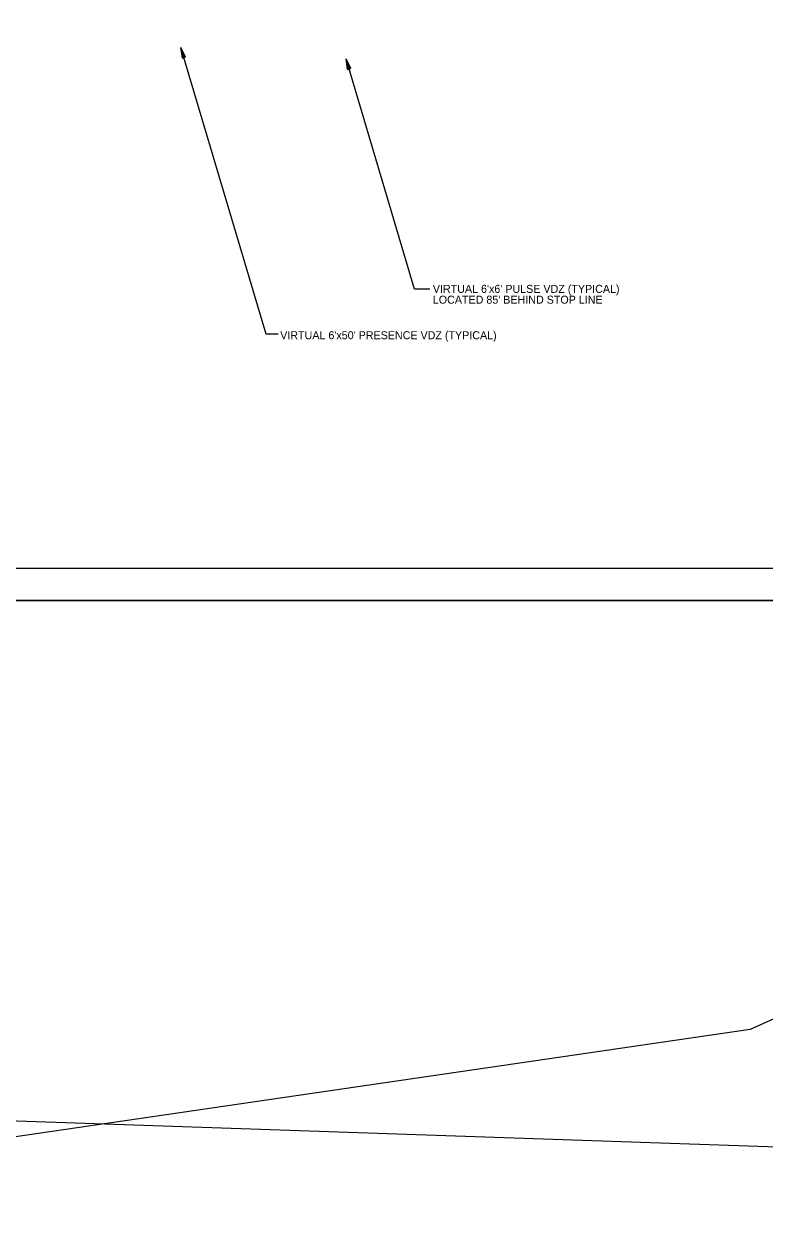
# Model space of a CAD drawing. Extents: x 660063 to 664816, y 641756 to 643817.
# Drawn here: x 661905.5 to 662183.1, y 642013.5 to 642464.6 of the extents above; entities that cross this region are included whole.
import ezdxf

# ---------------------------------------------------------------- set-up
doc = ezdxf.new("R2010")
doc.units = 0
for name, color, linetype in [('Default', 7, 'Continuous'), ('R_Border', 7, 'Continuous'), ('R_No Plot', 7, 'Continuous'), ('T_Drafting', 7, 'Continuous')]:
    doc.layers.add(name, color=color, linetype=linetype)

msp = doc.modelspace()

# ---------------------------------------------------------------- linework, layer by layer
at = {"layer": 'Default'}
for points in [[(662978.12, 642248.52), (662628.42, 642290.7), (662177.59, 642087.82)], [(662177.59, 642087.82), (661668.75, 642013.51), (660133.51, 642066.06)], [(663581.19, 642087.82), (663072.35, 642013.51), (661537.11, 642066.06)]]:
    msp.add_lwpolyline(points, dxfattribs=at)
at = {"layer": 'R_Border'}
msp.add_line((662396.53, 642260.59), (661447.99, 642260.59), dxfattribs=at)
at = {"layer": 'R_No Plot'}
msp.add_line((661410.79, 642248.66), (662410.79, 642248.66), dxfattribs=at)
msp.add_lwpolyline([(661410.77, 642888.66), (662410.79, 642888.66), (662410.79, 642248.64), (661410.77, 642248.64)], close=True, dxfattribs=at)
at = {"layer": 'T_Drafting'}
for p, q in [((661996.13, 642348.46), (661964.24, 642455.87)), ((661964.8, 642451.87), (661964.24, 642455.87)), ((661965.95, 642452.21), (661964.24, 642455.87)), ((661964.9, 642451.89), (661964.43, 642455.23)), ((661965.86, 642452.18), (661964.43, 642455.23)), ((661965.76, 642452.15), (661964.63, 642454.57)), ((661965, 642451.92), (661964.63, 642454.57)), ((661965.09, 642451.95), (661964.82, 642453.93)), ((661965.66, 642452.12), (661964.82, 642453.93)), ((661965.57, 642452.09), (661965.01, 642453.28)), ((661965.19, 642451.98), (661965.01, 642453.28)), ((661964.8, 642451.87), (661965.95, 642452.21)), ((661965.47, 642452.06), (661965.2, 642452.64)), ((661965.29, 642452.01), (661965.2, 642452.64)), ((662026.71, 642447.63), (662026.15, 642451.64)), ((662027.86, 642447.97), (662026.15, 642451.64)), ((662051.79, 642365.28), (662026.15, 642451.64)), ((662026.81, 642447.66), (662026.34, 642451)), ((662027.76, 642447.95), (662026.34, 642451)), ((662027.67, 642447.92), (662026.53, 642450.34)), ((662026.9, 642447.69), (662026.53, 642450.34)), ((662027, 642447.72), (662026.72, 642449.7)), ((662027.57, 642447.89), (662026.72, 642449.7)), ((662027.47, 642447.86), (662026.91, 642449.05)), ((662027.1, 642447.75), (662026.91, 642449.05)), ((662026.71, 642447.63), (662027.86, 642447.97)), ((662027.38, 642447.83), (662027.11, 642448.41)), ((662027.19, 642447.78), (662027.11, 642448.41)), ((662057.57, 642365.28), (662051.79, 642365.28)), ((662000.73, 642348.46), (661996.13, 642348.46))]:
    msp.add_line(p, q, dxfattribs=at)

# ---------------------------------------------------------------- texts
for s, p in [("VIRTUAL 6'x6' PULSE VDZ (TYPICAL)", (662058.65, 642363.9)), ("LOCATED 85' BEHIND STOP LINE", (662058.65, 642359.84)), ("VIRTUAL 6'x50' PRESENCE VDZ (TYPICAL)", (662001.45, 642346.52))]:
    msp.add_text(s, height=3, dxfattribs=at).set_placement(p)

doc.saveas('drawing.dxf')
